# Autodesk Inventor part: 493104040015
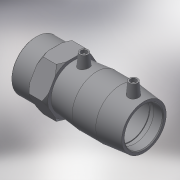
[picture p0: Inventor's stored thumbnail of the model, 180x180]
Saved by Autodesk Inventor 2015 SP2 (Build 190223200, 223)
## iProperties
Created: 2017-06
Part Number: 493104040015
Material: Generic
Description: PLASSON FEMALE TRANSITION COUPLER 40-1.1/2"
Document SubType Name: Modeling
Designer: KIM
Mass: 164.012 g
Surface Area: 420.235 cm^2
Volume: 164.012 cm^3
Density: 1 g/cm^3
Appearance: Default
Author: KIM
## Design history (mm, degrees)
derived "493104.ipt"
feature "Solid1::493104.ipt"
tag "TaggingFeature1"
body "Solid1"
other parameters: "d0" = 97, "d2" = 56, "d3" = 47, "d4" = 32.33333, "d5" = 50.4, "d6" = 38, "d8" = 168 deg, "d10" = 18.8, "d11" = 6.26667, "d29" = 46, "d30" = 14, "d31" = 33.95, "d34" = 5 deg, "d41" = 4, "d42" = 14, "d43" = 0, "d48" = 3, "d49" = 0, "d55" = 25, "d57" = 29, "d59" = 44.845, "d60" = 22.5, "d70" = 56, "d71" = 12.5, "d72" = 0, "d73" = 45 deg, "d74" = 2.9, "d75" = 45 deg, "d77" = 0.6, "d80" = 0.8, "L_" = 122, "L_1" = 47, "D_1" = 56, "A_" = 46, "d_2" = 12, "L_2" = 25, "D_" = 29, "R_p" = 44.845
